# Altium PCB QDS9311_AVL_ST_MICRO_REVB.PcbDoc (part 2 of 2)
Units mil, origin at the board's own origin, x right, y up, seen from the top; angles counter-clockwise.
Board outline 2100 x 2774 mil, 6 copper layers (Top Layer, GND, INT1, PWR1, PWR2, Bottom Layer), stack 63.834 mil thick; 64 components, 29 nets, 286 pads, 246 vias.
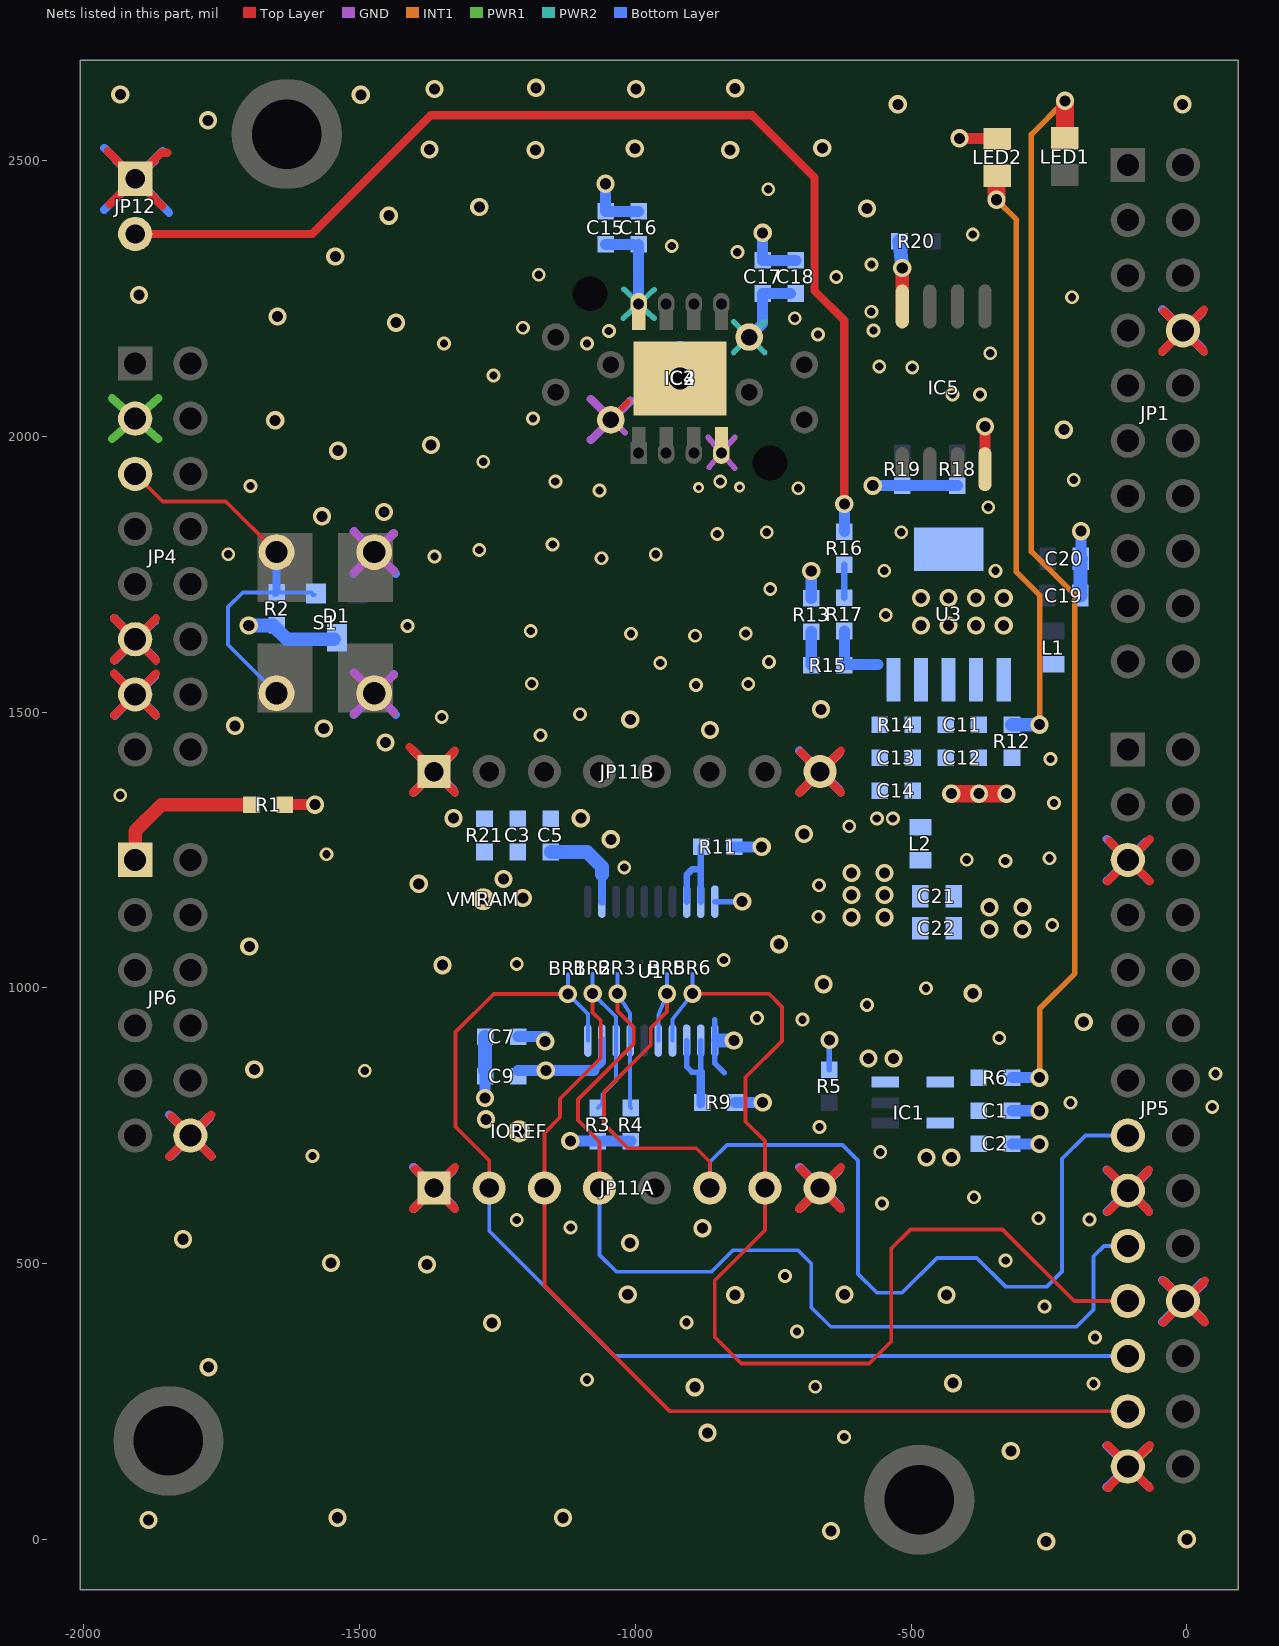
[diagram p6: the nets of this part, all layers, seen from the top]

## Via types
v1: diameter 33, hole 20, Top Layer to Bottom Layer, tented both sides, 143 vias
v2: diameter 25, hole 15, Top Layer to Bottom Layer, tented both sides, 101 vias
v3: diameter 20, hole 10, Top Layer to Bottom Layer, tented both sides, 2 vias

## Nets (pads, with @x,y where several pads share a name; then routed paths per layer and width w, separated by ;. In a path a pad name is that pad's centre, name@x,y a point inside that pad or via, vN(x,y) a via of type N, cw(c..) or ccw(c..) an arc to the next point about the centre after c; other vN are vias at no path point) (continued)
GND: C1.2 C2.2 C3.2 C5.2 C7.2 C9.2 C11.2 C12.2 C13.2 C14.2 C15.2 C16.2 C17.2 C18.2 C19.2 C20.2 C21.2 C22.2 IC1.3 IC2.4_EP IC2.9 IC3.4 IC4.4_EP IC4.9 IC5.4 JP1.8 JP4.11 JP4.13 JP5.5 JP5.17 JP5.22 JP5.27 JP6.12 JP11A.1 JP11A.8 JP11B.1 JP11B.8 JP12.1 LED2.C R9.1 R11.1 R13.2 R21.1 S1.3 S1.4 U1.11 U3.3 | length 13685.9
  Top Layer w10: IC3.4@-1044.39,2030 -1013.65,2062.41
  Top Layer w15: -1957,2517 JP12.1@-1907,2467 ; -1953,2421 JP12.1@-1907,2467 ; -1945,1494 JP4.13@-1907,1532 ; -1945,1570 JP4.13@-1907,1532 ; -1945,1594 JP4.11@-1907,1632 ; -1945,1670 JP4.11@-1907,1632 ; -1869,1494 JP4.13@-1907,1532 ; -1869,1570 JP4.13@-1907,1532 ; -1869,1594 JP4.11@-1907,1632 ; -1869,1670 JP4.11@-1907,1632 ; -1858,2418 JP12.1@-1907,2467 ; -1849,2514 -1860,2514 JP12.1@-1907,2467 ; -1845,694 JP6.12@-1807,732 ; -1841.21,766.21 JP6.12@-1807,732 ; -1769,694 JP6.12@-1807,732 ; -1769,770 JP6.12@-1807,732 ; -1409.5,1436.5 JP11B.1@-1365,1392 ; -1403,599 JP11A.1@-1365,637 ; -1403,1354 JP11B.1@-1365,1392 ; -1399.21,671.21 JP11A.1@-1365,637 ; -1327,599 JP11A.1@-1365,637 ; -1327,675 JP11A.1@-1365,637 ; -1327,1354 JP11B.1@-1365,1392 ; -1327,1430 JP11B.1@-1365,1392 ; -703,599 JP11A.8@-665,637 ; -703,1354 JP11B.8@-665,1392 ; -699.21,671.21 JP11A.8@-665,637 ; -699.21,1426.21 JP11B.8@-665,1392 ; -627,599 JP11A.8@-665,637 ; -627,675 JP11A.8@-665,637 ; -627,1354 JP11B.8@-665,1392 ; -627,1430 JP11B.8@-665,1392 ; -143.29,93.29 -105.29,131.29 -67.29,93.29 ; -143.29,170.71 -105.29,132.71 -67.29,170.71 ; -143.29,593.29 -105.29,631.29 -143.29,669.29 ; -143.29,1193.29 JP5.5@-105.29,1231.29 ; -139.5,1265.5 JP5.5@-105.29,1231.29 ; -69,594 JP5.17@-107,632 -69,670 ; -67.29,1193.29 JP5.5@-105.29,1231.29 ; -67.29,1269.29 JP5.5@-105.29,1231.29 ; -45,2154 JP1.8@-7,2192 ; -43.29,393.29 JP5.22@-5.29,431.29 ; -43.29,469.29 JP5.22@-5.29,431.29 ; -41.21,2226.21 JP1.8@-7,2192 ; 31,2154 JP1.8@-7,2192 ; 31,2230 JP1.8@-7,2192 ; 32.71,393.29 JP5.22@-5.29,431.29 ; 32.71,469.29 JP5.22@-5.29,431.29
  Top Layer w20: v1(-412,2540.47) LED2.C@-344,2540.47 ; IC5.4@-366,1940.5 v1(-366,2018)
  GND w10: IC3.4@-1042.69,2030.71 -1018.46,2006.48 ; -868,1998 IC2.4_EP@-844,1970 ; -866.29,1944 IC2.4_EP@-844,1970 ; IC2.4_EP@-842.29,1972 IC2.4_EP@-844,1970 ; -820,1942 IC2.4_EP@-844,1970 ; -820,1998 IC2.4_EP@-844,1970
  GND w15: -1943.29,1494.29 JP4.13@-1907,1530.59 ; -1943.29,1568.29 JP4.13@-1907,1532 ccw(c-1905.29,1533.71) JP4.13@-1905.29,1531.29 ; -1943.29,1594.29 JP4.11@-1907,1630.59 ; -1943.29,1668.29 JP4.11@-1907,1632 ccw(c-1905.29,1633.71) JP4.11@-1905.29,1631.29 ; -1943.29,2429.29 JP12.1@-1907,2465.59 ; -1943.29,2503.29 JP12.1@-1907,2467 ccw(c-1905.29,2468.71) JP12.1@-1905.29,2466.29 ; -1871.71,1497.71 JP4.13@-1905.29,1531.29 ; -1871.71,1564.88 JP4.13@-1905.29,1531.29 ; -1871.71,1597.71 JP4.11@-1905.29,1631.29 ; -1871.71,1664.88 JP4.11@-1905.29,1631.29 ; -1871.71,2432.71 JP12.1@-1905.29,2466.29 ; -1871.71,2499.88 JP12.1@-1905.29,2466.29 ; -1843.29,694.29 JP6.12@-1807,730.59 ; -1843.29,768.29 JP6.12@-1807,732 ccw(c-1805.29,733.71) JP6.12@-1805.29,731.29 ; -1771.71,697.71 JP6.12@-1805.29,731.29 ; -1771.71,764.88 JP6.12@-1805.29,731.29 ; -1509.71,1497.76 S1.3@-1473.42,1534.05 ; -1509.71,1571.75 -1473.42,1535.46 ccw(c-1471.71,1537.17) S1.3@-1471.71,1534.76 ; -1509.71,1753.66 S1.4@-1473.42,1789.95 ; -1509.71,1827.66 -1473.42,1791.37 ccw(c-1471.71,1793.08) S1.4@-1471.71,1790.66 ; -1438.12,1501.17 S1.3@-1471.71,1534.76 ; -1438.12,1568.34 S1.3@-1471.71,1534.76 ; -1438.12,1757.07 S1.4@-1471.71,1790.66 ; -1438.12,1824.25 S1.4@-1471.71,1790.66 ; -1401.29,600.71 JP11A.1@-1365,637 ; -1401.29,674.71 -1365,638.42 ccw(c-1363.29,640.12) JP11A.1@-1363.29,637.71 ; -1401.29,1355.71 JP11B.1@-1365,1392 ; -1401.29,1429.71 -1365,1393.42 ccw(c-1363.29,1395.12) JP11B.1@-1363.29,1392.71 ; -1329.71,604.12 JP11A.1@-1363.29,637.71 ; -1329.71,671.29 JP11A.1@-1363.29,637.71 ; -1329.71,1359.12 JP11B.1@-1363.29,1392.71 ; -1329.71,1426.29 JP11B.1@-1363.29,1392.71 ; -1080.69,1993.71 IC3.4@-1044.39,2030 ; -1080.69,2067.71 -1044.39,2031.42 ccw(c-1042.69,2033.12) -1042.69,2030.71 -1009.1,2064.29 ; -955.29,2067.29 IC2.9@-919,2103.59 ; -955.29,2141.29 IC2.9@-919,2105 ccw(c-917.29,2106.71) IC2.9@-917.29,2104.29 ; -883.71,2070.71 IC2.9@-917.29,2104.29 ; -883.71,2137.88 IC2.9@-917.29,2104.29 ; -701.29,600.71 JP11A.8@-665,637 ; -701.29,674.71 -665,638.42 ccw(c-663.29,640.12) JP11A.8@-663.29,637.71 ; -701.29,1355.71 JP11B.8@-665,1392 ; -701.29,1429.71 -665,1393.42 ccw(c-663.29,1395.12) JP11B.8@-663.29,1392.71 ; -629.71,604.12 JP11A.8@-663.29,637.71 ; -629.71,671.29 JP11A.8@-663.29,637.71 ; -629.71,1359.12 JP11B.8@-663.29,1392.71 ; -629.71,1426.29 JP11B.8@-663.29,1392.71 ; -145,95 JP5.27@-108.71,131.29 ; -145,169 JP5.27@-108.71,132.71 ; -143.29,594.29 JP5.17@-107,630.59 ; -143.29,668.29 JP5.17@-107,632 ; -143.29,1194.29 JP5.5@-107,1230.59 ; -143.29,1268.29 JP5.5@-107,1232 ccw(c-105.29,1233.71) JP5.5@-105.29,1231.29 ; -73.41,98.41 JP5.27@-107,132 -73.41,165.59 ; -71.71,597.71 JP5.17@-105.29,631.29 ; -71.71,664.88 JP5.17@-105.29,631.29 ; -71.71,1197.71 JP5.5@-105.29,1231.29 ; -71.71,1264.88 JP5.5@-105.29,1231.29 ; -43.29,2155.71 JP1.8@-7,2192 ; -43.29,2229.71 JP1.8@-7,2193.42 ; -41.58,393.59 JP5.22@-5.29,429.88 ; -41.58,467.59 JP5.22@-5.29,431.29 ; JP5.22@-8.71,432.71 ccw(c-7,434.42) JP5.22@-7,432 ; 28.29,2159.12 -5.29,2192.71 28.29,2226.29 ; 30,397 -3.58,430.59 30,464.17 ; JP5.17@-107,632 ccw(c-105.29,633.71) JP5.17@-105.29,631.29 ; JP5.17@-107,632 ccw(c-105.29,633.71) JP5.17@-105.29,631.29
  INT1 w15: -1943.29,1494.29 JP4.13@-1907,1530.59 ; -1943.29,1568.29 JP4.13@-1907,1532 ccw(c-1905.29,1533.71) JP4.13@-1905.29,1531.29 ; -1943.29,1594.29 JP4.11@-1907,1630.59 ; -1943.29,1668.29 JP4.11@-1907,1632 ccw(c-1905.29,1633.71) JP4.11@-1905.29,1631.29 ; -1943.29,2429.29 JP12.1@-1907,2465.59 ; -1943.29,2503.29 JP12.1@-1907,2467 ccw(c-1905.29,2468.71) JP12.1@-1905.29,2466.29 ; -1871.71,1497.71 JP4.13@-1905.29,1531.29 ; -1871.71,1564.88 JP4.13@-1905.29,1531.29 ; -1871.71,1597.71 JP4.11@-1905.29,1631.29 ; -1871.71,1664.88 JP4.11@-1905.29,1631.29 ; -1871.71,2432.71 JP12.1@-1905.29,2466.29 ; -1871.71,2499.88 JP12.1@-1905.29,2466.29 ; -1843.29,694.29 JP6.12@-1807,730.59 ; -1843.29,768.29 JP6.12@-1807,732 ccw(c-1805.29,733.71) JP6.12@-1805.29,731.29 ; -1771.71,697.71 JP6.12@-1805.29,731.29 ; -1771.71,764.88 JP6.12@-1805.29,731.29 ; -1509.71,1496.34 S1.3@-1473.42,1532.63 ; -1509.71,1570.34 S1.3@-1473.42,1534.05 ccw(c-1471.71,1535.76) S1.3@-1471.71,1533.34 ; -1509.71,1752.25 S1.4@-1473.42,1788.54 ; -1509.71,1826.25 S1.4@-1473.42,1789.95 ccw(c-1471.71,1791.66) S1.4@-1471.71,1789.25 ; -1438.12,1499.75 S1.3@-1471.71,1533.34 ; -1438.12,1566.93 S1.3@-1471.71,1533.34 ; -1438.12,1755.66 S1.4@-1471.71,1789.25 ; -1438.12,1822.83 S1.4@-1471.71,1789.25 ; -1401.29,599.29 JP11A.1@-1365,635.59 ; -1401.29,673.29 JP11A.1@-1365,637 ccw(c-1363.29,638.71) JP11A.1@-1363.29,636.29 ; -1401.29,1354.29 JP11B.1@-1365,1390.59 ; -1401.29,1428.29 JP11B.1@-1365,1392 ccw(c-1363.29,1393.71) JP11B.1@-1363.29,1391.29 ; -1329.71,602.71 JP11A.1@-1363.29,636.29 ; -1329.71,669.88 JP11A.1@-1363.29,636.29 ; -1329.71,1357.71 JP11B.1@-1363.29,1391.29 ; -1329.71,1424.88 JP11B.1@-1363.29,1391.29 ; -701.29,599.29 JP11A.8@-665,635.59 ; -701.29,673.29 JP11A.8@-665,637 ccw(c-663.29,638.71) JP11A.8@-663.29,636.29 ; -701.29,1354.29 JP11B.8@-665,1390.59 ; -701.29,1428.29 JP11B.8@-665,1392 ccw(c-663.29,1393.71) JP11B.8@-663.29,1391.29 ; -629.71,602.71 JP11A.8@-663.29,636.29 ; -629.71,669.88 JP11A.8@-663.29,636.29 ; -629.71,1357.71 JP11B.8@-663.29,1391.29 ; -629.71,1424.88 JP11B.8@-663.29,1391.29 ; -143.29,594.29 JP5.17@-107,630.59 ; -143.29,668.29 JP5.17@-107,632 ccw(c-105.29,633.71) JP5.17@-105.29,631.29 ; -143.29,1194.29 JP5.5@-107,1230.59 ; -143.29,1268.29 JP5.5@-107,1232 ccw(c-105.29,1233.71) JP5.5@-105.29,1231.29 ; -141.58,93.59 JP5.27@-105.29,129.88 ; -141.58,167.59 -105.29,131.29 ccw(c-103.58,133) JP5.27@-103.58,130.59 ; -71.71,597.71 JP5.17@-105.29,631.29 ; -71.71,664.88 JP5.17@-105.29,631.29 ; -71.71,1197.71 JP5.5@-105.29,1231.29 ; -71.71,1264.88 JP5.5@-105.29,1231.29 ; -70,97 JP5.27@-103.58,130.59 ; -70,164.17 JP5.27@-103.58,130.59 ; -43.29,2154.29 JP1.8@-7,2190.59 ; -43.29,2228.29 JP1.8@-7,2192 ccw(c-5.29,2193.71) JP1.8@-5.29,2191.29 ; -41.58,395 JP5.22@-5.29,431.29 ; -41.58,469 -5.29,432.71 ccw(c-3.58,434.42) JP5.22@-3.58,432 ; 28.29,2157.71 JP1.8@-5.29,2191.29 ; 28.29,2224.88 JP1.8@-5.29,2191.29 ; 30,398.41 JP5.22@-3.58,432 ; 30,465.59 JP5.22@-3.58,432
  Bottom Layer w10: U1.11@-855.83,900.56 -855.83,941.86 ; U1.11@-855.83,904.27 -855.83,862.97 -838.85,846
  Bottom Layer w15: -1963,2411 JP12.1@-1907,2467 ; -1963,2523 JP12.1@-1907,2467 ; -1945,1494 JP4.13@-1907,1532 ; -1945,1570 JP4.13@-1907,1532 ; -1945,1594 JP4.11@-1907,1632 ; -1945,1670 JP4.11@-1907,1632 ; -1872.79,1566.21 JP4.13@-1907,1532 ; -1872.79,1666.21 JP4.11@-1907,1632 ; -1869,1494 JP4.13@-1907,1532 ; -1869,1594 JP4.11@-1907,1632 ; -1857,2517 JP12.1@-1907,2467 ; -1845.5,2405.5 JP12.1@-1907,2467 ; -1845,694 JP6.12@-1807,732 ; -1845,770 JP6.12@-1807,732 ; -1772.79,766.21 JP6.12@-1807,732 ; -1769,694 JP6.12@-1807,732 ; -1510.42,1495.05 S1.3@-1472.42,1533.05 ; -1510.42,1571.05 S1.3@-1472.42,1533.05 ; -1510.42,1750.95 S1.4@-1472.42,1788.95 ; -1510.42,1826.95 S1.4@-1472.42,1788.95 ; -1438.21,1567.26 S1.3@-1472.42,1533.05 ; -1438.21,1823.16 S1.4@-1472.42,1788.95 ; -1434.42,1495.05 S1.3@-1472.42,1533.05 ; -1434.42,1750.95 S1.4@-1472.42,1788.95 ; -1403,599 JP11A.1@-1365,637 ; -1403,675 JP11A.1@-1365,637 ; -1403,1354 JP11B.1@-1365,1392 ; -1403,1430 JP11B.1@-1365,1392 ; -1330.79,671.21 JP11A.1@-1365,637 ; -1330.79,1426.21 JP11B.1@-1365,1392 ; -1327,599 JP11A.1@-1365,637 ; -1327,1354 JP11B.1@-1365,1392 ; -703,599 JP11A.8@-665,637 ; -703,675 JP11A.8@-665,637 ; -703,1354 JP11B.8@-665,1392 ; -703,1430 JP11B.8@-665,1392 ; -630.79,671.21 JP11A.8@-665,637 ; -630.79,1426.21 JP11B.8@-665,1392 ; -627,599 JP11A.8@-665,637 ; -627,1354 JP11B.8@-665,1392 ; -145,94 JP5.27@-107,132 ; -145,170 JP5.27@-107,132 ; -145,594 JP5.17@-107,632 ; -145,670 JP5.17@-107,632 ; -145,1194 JP5.5@-107,1232 ; -145,1270 JP5.5@-107,1232 ; -72.79,166.21 JP5.27@-107,132 ; -72.79,666.21 JP5.17@-107,632 ; -72.79,1266.21 JP5.5@-107,1232 ; -69,94 JP5.27@-107,132 ; -69,594 JP5.17@-107,632 ; -69,1194 JP5.5@-107,1232 ; -45,394 JP5.22@-7,432 ; -45,470 JP5.22@-7,432 ; -45,2154 JP1.8@-7,2192 ; -45,2230 JP1.8@-7,2192 ; 27.21,466.21 JP5.22@-7,432 ; 27.21,2226.21 JP1.8@-7,2192 ; 31,394 JP5.22@-7,432 ; 31,2154 JP1.8@-7,2192
  Bottom Layer w20: v1(-1272.39,800.26) C9.2@-1272.39,850.26 ; v1(-1054,2458) C15.2@-1054,2408 C16.2@-994,2408 ; R11.1@-820.88,1255.58 v1(-770.88,1255.58) ; R9.1@-819,792 v1(-769,792) ; v1(-769,2369) C17.2@-769,2319 C18.2@-709,2319 ; R13.2@-681,1706 v1(-681,1756) ; C2.2@-317,717 v1(-267,717) ; C1.2@-317,777 v1(-267,777) ; C20.2@-192,1778 v1(-192,1828)
  Bottom Layer w25: C9.2@-1272.39,850.26 C7.2@-1272.39,911.26 ; IC2.9@-919,2105 -919,2160.38 ; U1.11@-849.41,904.27 v1(-821.38,904.27) ; C19.2@-193,1711 -193,1777 C20.2@-192,1778
  other v1: -255,-4 0,0 -645,15 -1883,35 -1540,39 -1131,39 -319.13,160 -869,193 -892.15,275.69 -423.75,283 -1774,312 -1260,392 -819,443 -435.75,443 -1013.75,444 -620.75,443.84 -1377.75,498.04 -1552,501 -1009.71,537 -1820,544 -878.39,564 -1271.07,761.5 -1691,852 -577,872 -532,872 -187,938 -388,990 -658.96,1006.55 -1349.75,1041 -1700,1075 -739.58,1079 -358,1106 -298,1106 -358,1145.99 -298,1145.99 -1392.75,1188.57 -1044.56,1269.29 -694.06,1279 -1329.88,1307.58 -1098.88,1307.58 -1453,1445 -864.38,1467.24 -1565,1470 -1726,1475 -1009.17,1486.33 -663.29,1505 -482,1657 -432,1657 -382,1657 -332,1657 -482,1707 -432,1707 -382,1707 -332,1707 -1568.23,1855 -1456,1863 -1539,1974 -1370.75,1984 -223,2012 -1653,2029 -1434,2206 -1649,2217 -1900,2256 -1544,2326 -1447,2400 -580,2413 -1283,2416 -1181,2519 -828,2519 -1373,2520 -1001,2522 -661,2523 -1775,2573 -524,2602 -8,2602 -1497.84,2619.25 -1934,2620 -1364,2630 -999,2630 -819,2631 -1180,2632
  other v2: -621.42,185.57 -673.69,276.53 -169,282 -1087.57,289.41 -166.68,366 -707,376.53 -907.1,393.29 -257.97,422 -728.52,477.37 -328.55,505.47 -1117.35,565.35 -1215,579 -176.6,580.01 -268.73,582 -552.6,609 -386,620.21 -1585.6,695.04 -556,702 -666,747.46 46,784 -211,791.5 52,844 -1490.6,849.5 -340,909 -696.8,942.25 -779.4,945 -580,969 -473,999 -1215,1043 -839.81,1050.41 -244,1114 -668,1129 -667,1186 -1020,1218 -329,1230 -399,1232 -249,1235 -1560,1242 -612,1293 -562,1307 -533,1307 -241,1335 -1934,1349 -247,1415 -1172.05,1458 -1351,1491 -1100.51,1496 -889.91,1549 -1187.71,1551.35 -795.42,1551 -954.88,1589 -757.53,1591 -891.6,1638.36 -1007.98,1642 -799.6,1642.38 -1189.57,1647 -1413,1656 -545.95,1675.8 -755.28,1723 -548.51,1756.42 -347,1756 -1061.48,1779 -1364,1782 -1738,1786 -962.86,1785.9 -1283,1794 -1150,1804 -851.3,1823 -761.66,1825.98 -518,1826 -360.13,1871.19 -1065,1901.79 -704.6,1905.87 -1698,1910 -1145,1918 -846,1918 -205,1921 -1275.88,1954 -1185.74,2032.35 -425,2076 -375,2076 -1257,2110.38 -498,2124.77 -557.52,2126.61 -356.33,2150.59 -1347,2168.21 -1087.55,2168.21 -668.58,2184.5 -1048,2191 -568,2192 -1203.96,2197 -711,2214 -572,2225.92 -208,2252 -635.81,2289 -1175,2293 -571.62,2311.41 -815,2334 -934,2345 -388,2366 -759,2448
  other v3: -885.37,1907.13 -810.79,1907.77
H\O\L\D\: BR3.1 JP5.19 JP11A.4 R4.1 U1.17 | length 2002.2
  Top Layer w7: JP11A.4@-1065,637 -1065,720.88 -1104,759.88 -1104,797.39 -1003,898.39 -1003,928.63 -1032.37,958 v1(-1032.37,989.33)
  Bottom Layer w7: JP11A.4@-1065,637 -1065,515.77 -1034.23,485 -862,485 -823,524 -705.03,524 -680.96,499.92 -680.96,420.47 -645.74,385.25 -200.02,385.25 -169,416.27 -169,513.17 -150.17,532 JP5.19@-107,532 ; BR3.1@-1032.37,1024.78 v1(-1032.37,989.33) -1009.37,953 U1.17@-1009.37,904.27 -1009.37,783.37 R4.1@-1008,782
IOREF: C1.1 C2.1 C7.1 C9.1 D1.3 IC1.5 IOREF.1 JP4.3 R2.2 R3.2 R4.2 R5.2 U1.19 | length 790
  PWR1 w15: -1949,1995 JP4.3@-1907,2032 ; -1949,2069 JP4.3@-1907,2032 ; -1865,1995 JP4.3@-1907,2032 ; -1865,2069 JP4.3@-1907,2032
  Bottom Layer w10: R5.2@-648,851.5 v1(-648,905.5)
  Bottom Layer w14: -1075.18,850.26 -1060.55,864.89 U1.19@-1060.55,904.27
  Bottom Layer w20: C9.1@-1212.39,850.26 v1(-1162.39,850.26) -1075.18,850.26 ; C7.1@-1212.39,911.26 v1@-1162.39,911.26 ; v1(-1118,722) R3.2@-1068,722 ; R3.2@-1058,722 R4.2@-1008,722
  Bottom Layer w25: v1(-1701,1657) -1657,1657 -1632,1632 D1.3@-1546.5,1632
  other v1: -472,692 -427,692 -1163.39,902.8
MISO: BR6.1 JP5.21 JP11A.7 U1.14 | length 2005.1
  Top Layer w7: v1(-896.42,989.28) -757.8,989.28 -734,965.49 -734,903.8 -800,837.8 -800,757 -765,722 JP11A.7@-765,637 -765,560.38 -856,469.38 -856,367.04 -807.96,319 -575.82,319 -536,358.82 -536,526.91 -500.91,562 -334.04,562 -204.04,432 JP5.21@-107,432
  Bottom Layer w7: U1.14@-932.6,904.27 -932.6,943.05 v1(-896.42,989.28) BR6.1@-896.42,1024.74
MOSI: BR1.1 JP5.23 JP11A.2 U1.20 | length 2005.2
  Top Layer w7: JP11A.2@-1265,637 -1265,687 -1326,748 -1326,919.64 -1256.83,988.81 v1(-1122.39,988.81)
  Bottom Layer w7: JP11A.2@-1265,637 -1265,559 -1038,332 JP5.23@-107,332 ; BR1.1@-1122.39,1024.26 v1(-1122.39,988.81) -1086.14,952.56 U1.20@-1086.14,904.27
NetIC1_4: IC1.4 R6.1
NetJP12_2: JP12.2 R16.2 | length 2032.4
  Top Layer w15: JP12.2@-1907,2367 -1586,2367 -1371,2582 -787.75,2582 -675,2469.25 -675,2263.97 -621,2209.97 v1(-621,1877)
  Bottom Layer w20: R16.2@-621,1827 v1(-621,1877)
NetLED1_C: LED1.C R6.2 | length 1974
  Top Layer w32: LED1.C@-221,2540.47 v1(-221,2608.47)
  INT1 w10: v1(-267,837) -267,962 -203,1026 -203,1712 -282,1791 -282,2547.47 v1(-221,2608.47)
  Bottom Layer w20: R6.2@-317,837 v1(-267,837)
NetLED2_A: LED2.A R12.1 | length 1077.8
  Top Layer w32: v1(-345,2429) LED2.A@-345,2472.54
  INT1 w10: v1(-345,2429) -309,2393 -309,1754 -267,1712 v1(-267,1477)
  Bottom Layer w25: R12.1@-317,1477 v1(-267,1477)
NetR9_2: R9.2 U1.12 U1.13 | length 192.2
  Bottom Layer w10: U1.13@-907.01,904.27 -907.01,856.87 -897.39,847.26 -881.42,847.26 U1.12@-881.42,904.27
  Bottom Layer w15: R9.2@-881.42,789 -881.42,847.26
NetR11_2: R11.2 U1.8 U1.9 | length 177.9
  Bottom Layer w12: U1.8@-907.01,1156.24 -907.01,1204.65 -896.39,1215.26 -881.42,1215.26 ; U1.9@-881.42,1156.24 -881.42,1215.26 ; R11.2@-880.88,1255.58 -881.42,1255.05 -881.42,1215.26
NetR13_1: R13.1 R15.1 | length 61
  Bottom Layer w20: R15.1@-681,1585 R13.1@-681,1646
NetR14_1: R14.1 R15.2 R17.2 U3.5 | length 122
  Bottom Layer w20: R17.2@-621,1647 -621,1586 -560,1586
NetR16_1: R16.1 R17.1 | length 60
  Bottom Layer w12: R17.1@-621,1707 R16.1@-621,1767
R\S\T\: D1.1 JP4.5 R2.1 S1.1 S1.2 | length 752.8
  Top Layer w7: JP4.5@-1907,1932 -1857,1882 -1742.63,1882 S1.2@-1650.58,1789.95
  Bottom Layer w7: R2.1@-1654.5,1712 -1650.58,1715.92 R2.1@-1650.58,1717 ; S1.1@-1650.58,1534.05 -1738.67,1622.13 -1738.67,1690.33 -1712,1717 R2.1@-1650.58,1717 ; D1.1@-1587,1717 R2.1@-1650.58,1717 ; D1.1@-1584.5,1712 D1.1@-1582,1712
  Bottom Layer w15: R2.1@-1650.58,1717 S1.2@-1650.58,1789.95
SCLK: BR5.1 JP5.15 JP11A.6 U1.15 | length 2005.1
  Top Layer w7: v1(-942.42,989.28) -942.42,957 -972,927.42 -972,896 -1057,811 -1057,753 -1013,709 -889.57,709 -865,684.43 JP11A.6@-865,637
  Bottom Layer w7: U1.15@-958.19,904.27 -958.19,950.46 v1(-942.42,989.28) BR5.1@-942.42,1024.74 ; JP11A.6@-865,637 -865,684 -834,715 -624.5,715 -596,686.5 -596,481 -562,447 -516.26,447 -453.26,510 -381,510 -329,458 -253.82,458 -226,485.82 -226,690 -184,732 JP5.15@-107,732
VADC: JP6.1 R1.2 | length 282.9
  Top Layer w25: JP6.1@-1907,1232 -1907,1284 -1859,1332 R1.2@-1696,1332
VIN: C11.1 C12.1 L1.2 R12.2 U3.1 U3.2
VMRAM: C3.1 C5.1 C15.1 C16.1 C17.1 C18.1 C21.1 C22.1 IC2.8 IC3.8 IC4.8 IC5.8 L2.2 R1.1 R18.2 R19.2 R20.2 R21.2 U1.2 U1.10 VMRAM.1 | length 1152.5
  Top Layer w20: R1.1@-1636,1332 v1(-1581,1332)
  Top Layer w24: IC5.8@-516,2235.5 v1(-516,2305)
  PWR2 w10: -1022,2214 IC2.8@-994,2240 ; -1020.92,2267 -993,2241.07 IC2.8@-992.92,2241 ; -966,2214 IC2.8@-994,2240 ; -966,2266 IC2.8@-992.92,2241 ; -821.61,2152 IC3.8@-793.61,2180 ; -821.61,2208 IC3.8@-793.61,2180 ; -765.61,2152 IC3.8@-793.61,2180 ; -765.61,2208 IC3.8@-793.61,2180 ; IC2.8@-994,2240 IC2.8@-992.92,2241
  Bottom Layer w10: U1.10@-855.83,1156.24 v1(-806.22,1156.24)
  Bottom Layer w14: U1.2@-1060.55,1156.24 -1060.55,1205
  Bottom Layer w20: C15.1@-1054,2348 C16.1@-1004,2348 ; IC2.8@-994,2240 C16.1@-994,2348 ; IC3.8@-793.61,2180 -769,2204.61 C17.1@-769,2259 C18.1@-719,2259 ; v1(-569.5,1910.5) R19.2@-516,1910.5 R18.2@-416,1910.5
  Bottom Layer w25: C5.1@-1153.55,1246.26 -1087.57,1246.26 -1060.55,1219.24 -1060.55,1205 ; R20.2@-521,2354 v1(-516,2305)
  other v1: -608,1128.01 -548,1128.01 -1204,1163 -608,1168 -548,1168 -1239,1197 -608,1207.99 -548,1207.99
VOUT: C13.1 C14.1 L2.1 R14.2 U3.4 | length 100
  Top Layer w32: v1(-427,1352) v1(-377,1352) v1(-327,1352)
W\P\: BR2.1 JP5.25 JP11A.3 R3.1 U1.18 | length 2005.1
  Top Layer w7: v1(-1077.39,989.81) -1077.39,966.39 -1077.39,955.39 -1062.81,940.81 -1062.81,872.69 -1136.74,798.76 -1136.74,765.2 -1165,736.94 -1165,460 -937,232 JP5.25@-107,232
  Bottom Layer w7: BR2.1@-1077.39,1025.26 v1(-1077.39,989.81) -1034.96,947.37 U1.18@-1034.96,904.27 -1034.96,831.55 -1060,806.51 -1060,790 R3.1@-1068,782
pads on no net: D1.2 IC1.1 IC3.HOLE1.6_NP IC3.ORIGIN JP1.1 JP1.2 JP1.3 JP1.4 JP1.5 JP1.6 JP1.7 JP1.9 JP1.10 JP1.11 JP1.12 JP1.13 JP1.14 JP1.15 JP1.16 JP1.17 JP1.18 JP1.19 JP1.20 JP4.1 JP4.2 JP4.4 JP4.6 JP4.7 JP4.8 JP4.10 JP4.12 JP4.14 JP4.15 JP4.16 JP5.1 JP5.2 JP5.3 JP5.4 JP5.6 JP5.7 JP5.8 JP5.9 JP5.10 JP5.11 JP5.12 JP5.14 JP5.16 JP5.18 JP5.20 JP5.24 JP5.26 JP5.28 JP6.2 JP6.3 JP6.4 JP6.5 JP6.6 JP6.7 JP6.8 JP6.9 JP6.10 JP6.11 S1.

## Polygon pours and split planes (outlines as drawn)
VMRAM on Bottom Layer "VMRAM" (solid, remove dead copper, pour order 15): -1123.39,1262.26 -1124.39,1263.26 -1329.24,1263.26 -1329.24,1117 -1151.92,1117 -1123.39,1145.53
GND on Bottom Layer "GND" (solid, remove dead copper, pour order 13): -1998.43,2682 92.57,2682 93.57,-141 -2013.43,-178 -2013.43,2663
+5V0 on PWR2 "\" (solid, remove dead copper, pour order 17): -2007.1,1646 -1759,1646 -1726,1679 -1726,2248 -1600,2374 -360,2374 -295,2309 -295,1747 90,1747 93,1750 93,2680 -2005,2680
VMRAM on PWR2 "VMRAM" (solid, remove dead copper, pour order 18): -2006.9,1618 -1755,1618 -1693,1680 -1693,2230 -1574,2349 -383,2349 -328,2294 -328,1711 -327,1712 90,1712 90,15 93,-16 93,-92 -519,-94 -1829,-94 -2007,-92 -2009,-38 -2004,8
GND on INT1 "gnd" (solid, remove dead copper, pour order 11): -2007,2677 -2002,2682 93,2682 93,-130 91,-132 -2009,-132 -2007,-130
GND on GND "Top Layer-No Net" (solid, remove dead copper, pour order 14): -2047,2722 133,2722 133,2212 133,-157 -1042,-157 -2007,-157
IOREF on PWR1 "IOEREF" (solid, remove dead copper, pour order 16): -2047,2722 133,2722 133,2212 133,-157 -1042,-157 -2007,-157
GND on Top Layer "GND" (solid, remove dead copper, pour order 10): -2007,2682 93,2682 100,-118 -2008,-124 -2007,2682

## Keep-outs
Keep-Out Layer:
  lines w25: 93,8 93,2682 -2007,2682 -2007,8 -2007,-92 -1807,-92 -517,-92 93,-92 93,12

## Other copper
Top Layer:
  rectangle net GND: -1539,1475 -1414,1624.5
  rectangle net GND: -1538,1700 -1411,1857.26
  rectangle net VMRAM: -1301,1138 -1185.74,1216.28
  rectangle net GND: -1013.74,2047 -982,2104.29
  rectangle net GND: -1013.65,2155.75 -1002,2171
  rectangle net GND: -848,2106 -824.26,2154.29
  rectangle net GND: -824.35,2012 -810,2034
  rectangle net GND: -841,2034 -824.35,2054.25
  rectangle net GND: -856,2012 -824.35,2039.91
  rectangle net GND: -505,1606 -310,1731
  rectangle net VMRAM: -626,1111 -530,1225
  pour cut-out: -1019,2012 -1051.75,1966 -1037.98,1960 -1013.11,1974 -1016.2,1991
  pour cut-out: -1933,1910 -1934.25,1861 -1900,1810 -1829,1805 -1783.95,1820 -1722,1852 -1736.82,1874 -1817,1895 -1899,1908.95
  pour cut-out: -1893,1956 -1820,1959 -1821,1941.15 -1881.99,1940.5
  pour cut-out: -1168.69,694.11 -1205,717.48 -1202.11,764 -1143.43,790 -1129.1,761.45 -1138.26,703.94
  pour cut-out: -1202.42,1274 -1234,1220 -1204.57,1216 -1188.62,1255.05
  pour cut-out: -1744,2676 -1705,2608.47 -1567,2603.05 -1529,2670 -1590,2686 -1716,2680
  pour cut-out: -743,2181.37 -699.43,2154 -701.37,2107.24 -757.53,2107 -755.41,2168
  pour cut-out: -834,2163.5 -834.05,2103 -822.98,2098 -815,2154 -820.15,2163.26
  pour cut-out: -1039.2,1944 -1011.2,1926 -1009.2,1951 -1016.2,1961 -1033.2,1952
  pour cut-out: -376.16,1989.21 -376.17,1887 -410.29,1887 -557.43,1887 -557.43,2014.16 -523.59,2048 -405,2048 -388,2031 -388,2001.04
  pour cut-out: -882,2035 -879,2032 -856,2032 -856,1990 -874,1990 -881,1997 -881,2031
  pour cut-out: -1149.96,1173.62 -1000.96,1173.62 -963.06,1211.88 -912.58,1211.88 -829,1211.88 -826,1209 -827.31,1203.94 -806.72,1182.83 -817.1,1167.12 -806.72,1138.44 -833.97,1141.53 -869.67,1105.83 -869.67,1083.35 -896.89,1056.13 -1138.13,1056.13 -1210.25,1128.25 -1257.6,1128.25 -1277.23,1130.47 -1290.9,1187.03 -1252.65,1220.22 -1243.16,1223.25 -1200.31,1197 -1176.93,1173.62
  pour cut-out: -1026.5,2001.04 -998.5,1983.04 -996.5,2008.04 -1003.5,2018.04 -1020.5,2009.04
  pour cut-out: -1038.36,2159.13 -1031.29,2126.61 -1012.2,2142.87 -1010.08,2154.89 -1028.46,2160.55
  pour cut-out: -1721,1357 -1586,1357 -1572.79,1343.79 -1572.79,1306.72 -1720.72,1306.72 -1721,1307
  pour cut-out: -337,2333 -337,2185 -545,2185 -545,2333
  pour cut-out: -834.05,2270.08 -818.92,2254.95 -818.92,2218.16 -797,2196.23 -797,2154 -833,2154 -834,2155 -834,2172 -1010.22,2172 -1016,2177.78 -1016,2258.03 -1003.95,2270.08
  pour cut-out: -1175.38,594.04 -1170.41,609.6 -1157.68,626.57 -1145.66,625.86 -1142.83,620.21 -894,642 -865.8,607.57 -853.72,691.97 -830.28,657.04 -828.28,643.52 -824.91,642.09 -824.91,620.13 -851,594.04
  pour cut-out: -798.03,2054.05 -829,2054.05 -825.61,2064.66 -812.88,2081.63 -800.86,2080.92 -798.03,2075.26
  pour cut-out: -761.39,2144.17 -792.35,2144.17 -788.97,2154.78 -776.24,2171.75 -764.22,2171.04 -761.39,2165.38
  pour cut-out: -885.93,1016.39 -869.84,1000.29 -869.84,978.74 -887.52,961.05 -1132.22,961.05 -1143.43,972.26 -1143.43,1005.27 -1132.31,1016.39
  pour cut-out: -872.64,1978.39 -872.64,1974.15 -856.38,1957.89 -851.75,1940.92 -873.35,1940.92 -886.07,1928.19 -898.8,1940.92 -898.8,1950.81 -874.76,1974.86
  pour cut-out: -1051,1433 -737.66,1433 -721.43,1416.77 -721.43,1360.36 -756.04,1325.75 -771.29,1341 -1039.6,1341 -1063.66,1365.05 -1063.66,1433
  pour cut-out: -1251.43,1431.74 -1170.23,1431.74 -1170.23,1344.05 -1176.28,1338 -1246.42,1338 -1246.42,1424.62 -1251.43,1429.64
  pour cut-out: -693.61,2065.08 -693.31,2064.78 -625,2064.78 -625,1868.99 -621,1864.99 -621,1850.42 -669.15,1850.42 -676,1857.26 -676,1917.18 -674.51,1918.67 -674.51,1928.64 -728.23,1928.64 -755.61,1956.02 -755.61,2017.6 -708.44,2064.78 -689.03,2064.78
  pour cut-out: -611.6,1852.4 -549,1915 -549,1937.36 -608,1937.36 -608,1919 -617,1910
  pour cut-out: -1697.83,1486.8 -1426.17,1486.8 -1426.17,1837.2 -1697.83,1837.2
  pour cut-out: -1137.83,1181.52
  pour cut-out: -1133,1186 -1133,1184.66 -1145.66,1172 -1137.66,1164 -1133,1164 -1128,1169 -1132.31,1173.31 -1132.31,1185.59
  pour cut-out: -1064.69,1180 -1055.85,1171.16 -1070,1171.16 -1070,1178 -1068,1180
  text "TOP" at 583.71,938.28 h65
GND:
  text "GND" at 1959,788 h65
PWR1:
  text "PWR1" at 1977,643 h65
INT1:
  pour cut-out: -337,2449 -298,2472 -288,2463 -289,2446 -332,2432
  pour cut-out: -278.72,1724.94 -239.72,1747.94 -229.72,1738.94 -230.72,1721.94 -273.72,1707.94
  pour cut-out: -791.59,1881.33 -780.28,1925.17 -766.84,1925.88 -755.53,1913.15 -776.03,1872.85
  pour cut-out: -739.12,1983.92 -782.96,1995.24 -783.66,2008.67 -770.94,2019.98 -730.63,1999.48
  pour cut-out: -707.28,2027.13 -746.28,2004.13 -756.28,2013.13 -755.28,2030.13 -712.28,2044.13
  pour cut-out: -981.45,1963.8 -937.61,1952.49 -936.9,1939.05 -949.63,1927.74 -989.93,1948.24
  pour cut-out: -969,2000 -890.31,2000 -890.08,1999.77 -894,1995.85 -894,1939.92 -980.36,1939.92 -980.43,1940 -969,1951.44
  pour cut-out: -656,1969.96 -656,2042 -668.8,2054.8 -732.8,1990.81 -732.8,1885.8 -715.79,1868.79 -684.7,1868.79 -684.7,1922.65 -657.7,1949.65
  pour cut-out: -758,2131.19 -757.59,2026.92 -803.72,2042 -828.38,2075.42 -844.96,2083 -846,2098 -817.14,2130 -759,2131.69
  pour cut-out: -948,2071.69 -955.38,2060 -932,2061.05 -950.89,2073.11
  pour cut-out: -1015,2060.38 -1024,2050 -1030,2060.38 -1014.29,2061.05
  pour cut-out: -885,1989.74 -858,1987 -864.29,1950.26 -882,1947.27 -885.04,1989
  pour cut-out: -642.35,1448.7 -641.58,1449.47 -601,1449.47 -601,1475.79 -599.79,1477 -602.47,1479.68 -627.32,1479.68 -645,1462 -642.35,1459.35
  pour cut-out: -1019,1940
  pour cut-out: -1007.57,1940
  pour cut-out: -1014.64,1943 -1006.1,1934.46 -1006.1,1944.62 -1007.72,1943
  text "INTERNAL1" at 564.54,800.05 h65
PWR2:
  pour cut-out: -295,1747
  pour cut-out: -305.42,1646.45 -321.12,1630.75 -493.34,1630.75 -508.25,1645.66 -508.25,1717.88 -492.88,1733.26 -367.74,1733.26 -359.73,1741.27 -359.73,1753.13 -335.36,1777.51 -315.82,1777.51 -305.42,1767.1
  text "PWR2" at 1939,343 h65
Bottom Layer:
  rectangle net VMRAM: -854.22,1140 -805,1171.92
  rectangle net B_MOSI: -1137.17,1042.36 -1107.37,1084.74
  region net MOSI: -1107.62,1029.15 -1137.42,1029.15 -1137.42,986.78 -1107.62,986.78
  rectangle net B\_\W\P\: -1092.17,1043.36 -1062.37,1085.74
  region net W\P\: -1062.62,1030.15 -1092.42,1030.15 -1092.42,987.78 -1062.62,987.78
  rectangle net B\_\H\O\L\D\: -1047.14,1042.89 -1017.35,1085.26
  region net H\O\L\D\: -1017.6,1029.68 -1047.39,1029.68 -1047.39,987.31 -1017.6,987.31
  rectangle net B\_\C\S\: -1002.17,1042.86 -972.37,1085.24
  region net C\S\: -972.62,1029.65 -1002.42,1029.65 -1002.42,987.28 -972.62,987.28
  rectangle net B_SCLK: -957.19,1042.84 -927.39,1085.21
  region net SCLK: -927.65,1029.63 -957.44,1029.63 -957.44,987.26 -927.65,987.26
  rectangle net B_MISO: -911.19,1042.84 -881.39,1085.21
  region net MISO: -881.65,1029.63 -911.44,1029.63 -911.44,987.26 -881.65,987.26
  region net IOREF: -1145.39,929.26 -1227.39,929.26 -1227.39,819.26 -1145.39,819.26
  rectangle net IOREF: -497,667 -352,717
  rectangle net NetIC1_4: -477,817 -352,864.5
  rectangle net IOREF: -477,667 -352,807
  rectangle net VOUT: -512,1276 -287,1377
  rectangle net NetR14_1: -577,1447 -519,1607
  rectangle net VOUT: -512,1327 -467,1607
  rectangle net GND: -575.7,1617 -287,1852
  rectangle net GND: -457,1392 -412,1795.11
  rectangle net VIN: -402,1387 -287,1447
  rectangle net VIN: -402,1387 -347,1607
  rectangle net VIN: -402,1512 -288.3,1607
  region net IOREF: -463,751 -497,717 -479,699 -445,733
  rectangle net VIN: -400,1508 -210,1605
  rectangle net GND: -335,671 -245,807
  rectangle net VMRAM: -633,1088 -457,1249
  region net GND: -274,1201 -439,1201 -439,1076 -274,1076
  rectangle net GND: -577,1276 -519,1438
  rectangle net GND: -1349,1288 -1081,1327
  pour cut-out: -516.27,1297 -539,1258 -516.27,1255.05 -514,1281
  pour cut-out: -282.53,1686 -287.74,1612 -266.54,1612 -261.44,1668 -272.63,1682
  pour cut-out: -600,1653 -558,1611.21 -594,1607 -607.54,1628.57
  pour cut-out: -711.44,1628.98 -711,1611.21 -701.82,1609 -699.43,1621 -702.03,1631
  pour cut-out: -594.78,1640 -568,1616 -590.9,1612.81 -599.15,1612 -596,1632
  pour cut-out: -1208.56,1109.48 -1146.12,1062 -1147.41,1083.24 -1174.58,1113.92 -1185,1116.4
  pour cut-out: -895.11,771 -965,751.24 -970.89,774 -953.47,794 -898.37,801
  pour cut-out: -1147.85,982 -1173,938.91 -1131.47,935.03 -1140.77,965
  pour cut-out: -1159,818 -1136,736 -1120,741 -1152.24,821
  pour cut-out: -340.44,2299.9 -302.74,2249 -338,2245 -358,2291
  pour cut-out: -338.26,2228 -382,2191 -384.79,2217.67 -379.14,2230 -367,2238.9
  pour cut-out: -268.58,1636 -287.74,1612 -200.3,1607.72 -212,1629.96 -247.58,1628 -267.63,1638.36
  pour cut-out: -1561,1608 -1620,1549 -1644.52,1607.42 -1642,1615
  pour cut-out: -1571.35,1743.5 -1525.35,1743.5 -1535.35,1729.5 -1579.35,1730.5
  pour cut-out: -1615,1769 -1599,1741 -1617.5,1735.59 -1627,1769
  pour cut-out: -531,818 -482,824 -482,803 -493,791 -523,788
  pour cut-out: -546,738 -503,698 -507,729.5 -516,742
  pour cut-out: -855.83,943.88 -880.88,943.88 -908.83,937.88 -887.83,925.88 -864.83,924.88 -860.83,925.88
  pour cut-out: -823.57,2270.71 -794.46,2267.77 -788.84,2284.3 -823.43,2285.29
  pour cut-out: -536,2299 -556,2262 -529,2252 -515,2262
  pour cut-out: -628.54,2181.59 -607.54,2144.59 -599.54,2150.59 -597.42,2172 -603.54,2179.59
  pour cut-out: -998.14,2209.92 -874.81,2209.92 -877.13,2226.14 -957,2228 -1053,2222.08 -1010.29,2222.08
  pour cut-out: -970,2324.5 -928.65,2310.3 -911,2289.5 -936,2280.5 -979,2307.5
  pour cut-out: -1077,2345 -1099,2306 -1083,2295 -1073,2307 -1067,2319
  pour cut-out: -1074.77,2218.19 -1113.77,2188.19 -1121.77,2210.19 -1116.27,2230.69
  pour cut-out: -1138.53,2245.73 -1163,2207 -1135,2204 -1120,2212 -1105,2233 -1119,2255
  pour cut-out: -1116.88,2141.32 -1129.68,2138.07 -1117.68,2122.07 -1076.57,2129.45 -1066.63,2141.32
  pour cut-out: -998.92,2071.35 -1000.92,2081.84 -1000.92,2049.35 -987.08,2048.65 -977.57,2045.71 -984.04,2052.18 -979.92,2075.35
  pour cut-out: -824,2000 -861,1995 -957.5,1995 -942.85,1943.73 -832.62,1942.66 -826.27,1947.27 -802,1966 -799.83,1988.41 -803,2007
  pour cut-out: -606.62,1865.75 -550.05,1889.8 -571.62,1896.3 -608.03,1899.69
  pour cut-out: -416,1266 -453,1234 -457,1261 -450,1276
  pour cut-out: -590.54,2102 -577.54,2089 -577.54,2030 -629.54,2030 -637.54,2038 -592.54,2083 -592.54,2102
  pour cut-out: -541,1945.5 -391,1945.5 -391,1935.5 -539.68,1935.5 -541,1934.19
  pour cut-out: -541,1995.5 -541,2009 -532,2018 -516,2018 -516,1993 -523,1986 -532.5,1995.5
  pour cut-out: -391,1995.5 -391,2040.58 -395,2044.58 -413.91,2044.58 -424.5,2034 -431,2034 -431,2012 -411,1992 -407.5,1995.5
  pour cut-out: -878.39,1076.26 -838.85,1115.8 -838.85,1228.41 -900.25,1228.41 -945.39,1183.26 -945.39,1022.26 -912.39,989.26 -881.39,989.26 -878.39,992.26
  pour cut-out: -347.54,811.46 -352,807 -357,812 -357,874 -266.87,874 -240.75,847.88 -240.75,825.66 -254.95,811.46
  pour cut-out: -646,1852 -596,1852 -596,1632 -646,1632
  pour cut-out: -660,1673 -597,1673 -596,1672 -596,1560 -656,1560 -660,1564
  pour cut-out: -667.3,2126.92 -655.99,2085.91 -665.89,2084.5 -682.53,2098.14 -683.57,2107.83
  pour cut-out: -768.53,2176.1 -757.22,2135.09 -767.12,2133.68 -783.76,2147.32 -784.8,2157.01
  pour cut-out: -791.05,2245.75 -779.74,2204.74 -789.64,2203.32 -806.27,2216.96 -807.31,2226.66
  pour cut-out: -1118.1,1178.88 -1077.39,1178.88 -1077.39,1192.31 -1081.35,1196.26 -1100.73,1196.26
  pour cut-out: -1046.21,1198.03 -1044.24,1200 -934.39,1200 -902.39,1232 -842.45,1232 -838.85,1228.41 -838.85,1178.88 -1051.59,1178.88 -1046.86,1183.61 -1046.86,1198.03
  pour cut-out: -855.88,1280.58 -855.46,1281 -849.42,1281 -849.42,1226.08 -851,1224.5 -852.08,1225.58 -855,1225.58 -855,1229.69 -855.88,1230.58
  pour cut-out: -623,826.5 -623,766.26 -625,764.26 -625.66,764.92 -698,764.92 -698,818.08 -688.92,818.08 -673,834 -665.5,826.5
  pour cut-out: -527.23,2206.69 -547.23,2169.69 -520.23,2159.69 -506.23,2169.69
  pour cut-out: -496,2379 -436,2379 -436,2328.08 -430.88,2322.96 -426.26,2327.58 -362.17,2327.58 -361.84,2327.26 -364.17,2324.92 -364.17,2285.38 -365.62,2285.38 -372.77,2278.23 -537.23,2278.23 -546,2287.01 -546,2379 -543.63,2381.37 -494,2381.37
  pour cut-out: -1179,2095.5 -1179,2193.31 -1179,2208.29 -1134.64,2252.66 -1125.98,2244 -1112,2244 -1112,2112 -1083.65,2083.65 -1107.52,2059.78 -1131.03,2047.53 -1156.25,2068.7 -1159,2065.95 -1179.43,2086.37 -1179.43,2095
  pour cut-out: -1018.89,1994.23 -997.7,1994.23 -996.92,2009.56 -1000.45,2012.59 -998.35,2014 -1023.05,2014 -1026.29,2017.24 -1026.86,1999.62
  pour cut-out: -563.66,2108.96 -584.66,2071.96 -592.66,2077.96 -594.78,2099.37 -588.66,2106.96
  pour cut-out: -797.96,2274 -797.23,2273.28 -684,2273.28 -684,2289.57 -683.57,2290 -817,2290 -812,2285 -812,2273.86 -798.63,2273.86 -797.96,2274.53
  pour cut-out: -1118.24,1108.97 -1117.2,1110 -871.49,1110 -863,1101.51 -863.33,1101.18 -863.33,942.05 -1097.74,942.05 -1129.68,974 -1138,974 -1148.65,984.65 -1148.65,1093.59 -1132.37,1109.87 -1114.42,1109.87
  pour cut-out: -969,809.5 -965,805.48 -965,697 -1109.5,697 -1100.73,705.78 -1100.73,742.1 -1097.9,742.1 -1093,747 -1093,838 -1085,846 -1005.5,846
  pour cut-out: -980.53,856.18 -976.79,859.93 -976.79,860
  pour cut-out: -974.4,864.6 -929.8,864.6 -904,838.79 -904,817 -854.22,817 -863.33,826.11 -863.33,866.49 -972.41,866.49 -974.4,864.5
  pour cut-out: -1103.11,881.64 -1103.11,860.98 -1110.09,854 -1124.64,854 -1145.39,874.75 -1145.39,939.35 -1234.31,939.35 -1237.48,936.17 -1237.48,914.98 -1187,864.5 -1178.76,872.74 -1153.74,872.74 -1143,862 -1097.7,845.04
  pour cut-out: -949.54,2073.11 -953.43,2132.45 -966.65,2132 -986.65,2104 -969.82,2070.34
  pour cut-out: -984,2010 -982,2012 -851.53,2012 -844,2019.53 -844,2039 -838,2045 -823,2030 -823,2002.5 -835.5,1990 -966,1990 -966,1992.25 -983.75,2010
  pour cut-out: -734,2234 -744,2234 -744,2238.9 -739.9,2243 -734,2243
  pour cut-out: -468.29,2091.57 -471.23,2062.46 -454.7,2056.84 -453.71,2091.43
  pour cut-out: -681.21,1846.43 -627,1846.43 -627,1871 -626.62,1871.38 -661,1871.38 -661,1866.64
  pour cut-out: -666.96,1935.06 -698.11,1935.06 -714.5,1918.67 -729.74,1933.91 -805.17,1933.91 -805.17,1934.01 -812.31,1941.15 -836.25,1941.15 -836.25,1953.25 -837,1954 -821,1970 -717.62,1970 -705.26,1957.63 -666.65,1957.63 -666.65,1934.75
  pour cut-out: -651.34,1917.84 -628.34,1974.84 -648.18,1964.19 -676.34,1940.84
  pour cut-out: -785.62,1884 -729.05,1908.04 -750.62,1914.54 -787.03,1917.94
  pour cut-out: -718.62,1886.39 -662.05,1910.43 -683.62,1916.93 -720.03,1920.33
  pour cut-out: -872.6,2206.26 -871.47,2204.83 -871.47,2200.95 -870.45,2200.95 -861,2210.4 -866.19,2215.58 -866.19,2217.67 -876.67,2217.67 -880.34,2214
  pour cut-out: -1024.91,2051 -1006.69,2069.22 -1001.09,2069.22 -984.04,2052.18 -989,2047.22 -989,1989.5 -1017.59,1989.5 -1026.86,1998.77 -1026.86,2048.22 -1025.45,2049.62 -1020.41,2044.58 -1014.96,2044.58 -1014.96,2049.75 -1023.04,2057.83
  pour cut-out: -1019,2373 -1029,2373 -1029,2368.1 -1019,2368.1
  pour cut-out: -1674.87,1721.65 -1674.87,1767.65 -1660.87,1757.65 -1661.87,1713.65
  pour cut-out: -1513,1600 -1476,1637 -1476,1687 -1517,1687 -1543,1661 -1543,1600
  pour cut-out: -1098.88,881.64 -1142.58,881.64 -1142.58,872.08 -1139.12,868.62 -1136.74,871 -1098,871 -1098,880.69 -1099.31,882
  text "BOTTOM" at 1941.54,938.05 h65

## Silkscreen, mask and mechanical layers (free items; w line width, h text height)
Top Overlay:
  drawing of 1942 lines, arcs and shapes, not listed
  text "+5V" at -429,2612 h50
  text "ACT" at -238,2610 h50
  text "1" at -136,2557 h34
  text "2" at 1,2556 h34
  text "1" at -1986,2450 h35
  text "INSERT JUMPER FOR" at -1840,2393 h35
  text "3V3 OPERATION" at -1843.37,2318.53 h35
  text "REMOVE FOR 1V8" at -1839.37,2250.91 h35
  text "GND" at 46,2233 h34 r270
  text "NC" at -1726,2130 h35
  text "1" at -1987,2113 h35
  text "IOREF" at -1725,2060 h35
  text "RST" at -1711,1962 h34
  text "+5V0" at -1738,1862 h34
  text "1" at -187,1421 h34
  text "2" at 59,1420 h34
  text "RESET" at -1670,1402.38 h50
  text "B_MOSI" at -1293,1329 h35 r270
  text "B_CS*" at -971,1329 h35 r270
  text "B_SCLK" at -863,1327.84 h35 r270
  text "B_WP*" at -1176,1326 h35 r270
  text "B_MISO" at -756.71,1326.42 h35 r270
  text "B_HOLD*" at -1056,1325 h35 r270
  text "1" at -1988,1211 h35
  text "GND" at -257,1199 h34
  text "VADC" at -1725,1168 h34
  text "CS*" at -253,826 h34
  text "SCLK" at -279,726 h34
  text "GND" at -1733,711 h34
  text "QSPI" at -374,684 h34 r270
  text "GND" at -272,627 h34
  text "MOSI" at -1284,567 h35 r270
  text "SCLK" at -878,567 h35 r270
  text "GND" at -1386,566 h35 r270
  text "HOLD*" at -1078.3,566.35 h35 r270
  text "CS*" at -981,566 h35 r270
  text "WP*" at -1183,564 h35 r270
  text "GND" at -679,563 h35 r270
  text "MISO" at -776,562 h35 r270
  text "HOLD*" at -308,514 h34
  text "MISO" at -284,421 h34
  text "MOSI" at -286,314 h34
  text "PN: ST_MICRO4 Rev. B" at -1509,215 h50
  text "WP*" at -266,215 h34
  text "TOP SILKSCREEN" at 556.96,195.06 h65
  text "GND" at -263,119 h34
  text "QDS9311_AVL_Rev.B" at -417,-58 h35
Bottom Overlay:
  rectangle: -1642,-50 -627,273
  text "JP1" at -42,2584.78 h60
  text "JP12" at -1834,2540 h45
  text "GND" at 80,2234.81 h34 r90
  text "JP4" at -1577,2078 h60
  text "B_HOLD*" at -1042,1664.6 h35 r90
  text "B_SCLK" at -848.93,1638.36 h35 r90
  text "B_MOSI" at -1246,1628 h35 r90
  text "B_MISO" at -753,1626 h35 r90
  text "B_WP*" at -1144.91,1609 h35 r90
  text "B_CS*" at -951.54,1609 h35 r90
  text "GND" at -1352,1556 h35 r90
  text "JP11B" at -1441,1362 h50
  text "VADC" at -1847.74,1301 h34
  text "GND" at -174,1198.63 h34
  text "CS*" at -169,815.19 h34
  text "GND" at -1654.19,713 h34
  text "SCLK" at -168,710 h34
  text "GND" at -178,612.6 h34
  text "JP11A" at -1445,602 h50
  text "JP6" at -1782,585 h60
  text "GND" at -1352,569 h35 r90
  text "CS*" at -941.11,567 h35 r90
  text "WP*" at -1145.39,565 h35 r90
  text "MOSI" at -1251.43,564.62 h35 r90
  text "HOLD*" at -1049.22,564 h35 r90
  text "MISO" at -748,564.6 h35 r90
  text "GND" at -644.25,564 h35 r90
  text "SCLK" at -841,563 h35 r90
  text "HOLD*" at -181,513 h34
  text "GND" at 81.43,468.09 h34 r90
  text "MISO" at -178,417 h34
  text "MOSI" at -176,310 h34
  text "WP*" at -179,222 h34
  text "BOTTOM SILKSCREEN" at 1928.96,185.06 h65
  text "GND" at -179,130 h34
  text "JP5" at -21,-4 h60
Top Solder:
  text "TOP SOLDERMASK" at 559,39 h65
Bottom Solder:
  text "BOTTOM SOLDERMASK" at 1930,46 h65
Dimension:
  lines w6: -2007,631 -2007,632 -2007,532 -1807,532
  lines w10: -2007,632 -2007,2682 93,2682 93,632 -417,632 -517,532 -1807,532 -1907,632 -2007,632
Outline:
  lines w8: 93,2682 93,2682
  lines w10: 469.65,0.93 3219.65,0.93 ; 469.65,150.93 3219.65,150.93 ; 469.65,300.93 3219.65,300.93 ; 469.65,450.93 3219.65,450.93 ; 469.65,600.93 3219.65,600.93 ; 469.65,750.93 3219.65,750.93 ; 469.65,900.93 3219.65,900.93 ; 469.65,1050.93 3219.65,1050.93 ; 469.65,1200.93 3219.65,1200.93 ; 469.65,1476.19 3219.65,1476.19 ; 469.65,1651.19 3219.65,1651.19 ; 469.65,1776.19 3219.65,1776.19 ; 469.65,1901.19 3219.65,1901.19 ; 469.65,2026.19 3219.65,2026.19 ; 469.65,2151.19 3219.65,2151.19 ; 469.65,2276.19 3219.65,2276.19 ; 469.65,2401.19 3219.65,2401.19 ; 469.65,2526.19 3219.65,2526.19 ; 469.65,2776.19 3219.65,2776.19 ; 1219.84,1526.19 1219.84,2776.19 ; 1844.65,-149.07 1844.65,1200.93 ; 3219.65,-148.89 469.65,-148.89 ; 469.65,-148.89 3219.98,-148.89 3219.98,-1078.9 469.65,-1078.9 469.65,-148.89 ; 469.65,1526.19 469.65,3926.19 3219.65,3926.19 3219.65,1526.19 ; 469.65,1526.19 3219.65,1526.19 ; 469.65,1526.19 469.65,-149.07 3219.65,-149.07 3219.65,1526.19 ; -2007,-92 -2007,8 -2007,2682 93,2682 93,8 93,-92 -517,-92 -1807,-92 -2007,-92
  text "Q DESIGN SERVICES, INC." at 1008.17,3580.18 h100
  text "2528 QUME DRIVE SUITE13" at 1261,3446 h60
  text "SAN JOSE, CA 95131" at 1311.54,3338.04 h60
  text "TEL: 408-428-9253" at 1327.54,3226.04 h60
  text "FAX: 408-428-9473" at 1331.54,3102.04 h60
  text "EMAIL: QHO@QDESIGNSERVICES.COM" at 1063,2969 h60
  text "Title:" at 841.57,2629.6 h75
  text "ST_MICRO4 Rev. B" at 1280.21,2624.8 h65
  text "Customer:" at 648.08,2439.33 h65
  text "Contact:" at 732.08,2308.33 h65
  text "CUST P/N#:" at 570.08,2184.33 h65
  text "JOB#:" at 854.18,1940.12 h65
  text "QDS9311_AVL_Rev. B" at 1347.21,1936.8 h65
  text "ENG./Designer:" at 547.08,1815.33 h65
  text "Quoc Ho" at 1353.71,1808.12 h65
  text "Scale:" at 860.08,1687.33 h65
  text "1 TO 1" at 1353.71,1683.12 h65
  text "View:" at 871.57,1559.6 h65
  text "TOP VIEW" at 1353.71,1558.12 h65
  text "DATE PLOTTED:" at 631.38,1291.87 h65
  text ".Print_Date" at 1958.18,1285.17 h65
  text "PADMASTER" at 583.71,1088.28 h65
  text "DRILLMASTER" at 1958.71,1088.28 h65
  text "PROPRIETARY NOTICE" at 977.5,-298.49 h100
  text "THIS DOCUMENT/FILE AND THE TECHNICAL" at 642.16,-427.48 h75
  text "DATA HEREIN DISCLOSED ARE PROPRIETARY" at 646.06,-551.86 h75
  text "TO Q DESIGN AND SHALL NOT BE DUPLICATED" at 623.17,-679.82 h75
  text "USED, RELEASED, OR DISCLOSED IN" at 641,-802.38 h75
  text "WHOLE OR IN PART WITHOUT EXPRESSED" at 639.63,-922.88 h75
  text "WRITTEN PERMISSION." at 646.25,-1043.84 h75
Mechanical:
  lines w5: -1907,1212.32 -1907,1232 ; -1907,2112.32 -1907,2132 ; -1008.97,611.72 -1008.97,626.49 ; -7,712.32 -7,732 ; -7,1572.32 -7,1592
  lines w10: -1072,1672 -1002,1672 ; -1002,1602 -1002,1672 ; -1002,1742 -1002,1672 ; -932,1672 -1002,1672 ; -2007,632 -1907,632 -1807,532 -517,532 -417,632 93,632 93,2682 -2007,2682 -2007,632 ; -1712,2682 -187,2682 -1712,2682 ; -1697.83,1486.8 -1697.83,1837.2 -1426.17,1837.2 -1426.17,1486.8 -1697.83,1486.8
